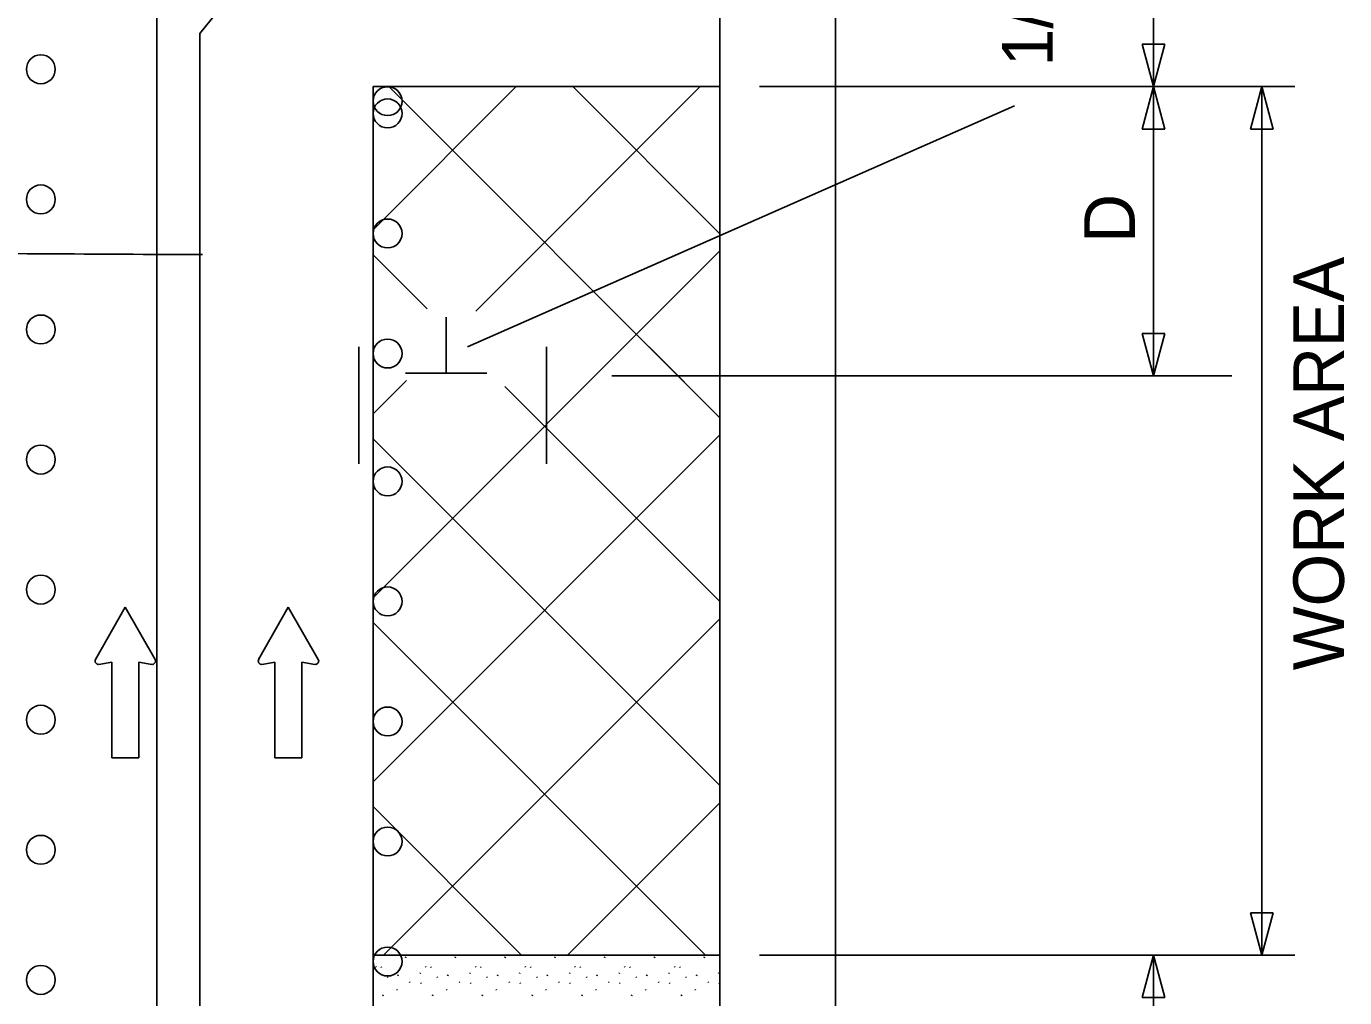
# Model space of a CAD drawing. Extents: x 16525 to 18475, y 5726 to 6926.
# Drawn here: x 16973 to 17155.5, y 6419.4 to 6553.8 of the extents above; entities that cross this region are included whole.
import ezdxf

# ---------------------------------------------------------------- set-up
doc = ezdxf.new("R2010")
doc.units = 0
for name, color, linetype in [('ALI_LEGAL_EX', 7, 'Continuous'), ('MT_SCRATCH_LEVEL_A', 7, 'Continuous'), ('MT_SCRATCH_LEVEL_E', 7, 'Continuous'), ('PAVT_EDGE_EX', 7, 'Continuous'), ('TRAFFIC_SIGNS_PR', 7, 'Continuous'), ('TYPICAL_TEXT_DIMEN_PR', 7, 'Continuous')]:
    doc.layers.add(name, color=color, linetype=linetype)

msp = doc.modelspace()

# ---------------------------------------------------------------- linework, layer by layer
at = {"layer": 'ALI_LEGAL_EX'}
for points in [[(17019, 6509.42), (17019, 6493.24)], [(17019, 6509.42), (17019, 6493.24)], [(17045, 6509.42), (17045, 6493.24)], [(17045, 6509.42), (17045, 6493.24)]]:
    msp.add_lwpolyline(points, dxfattribs=at)
at = {"layer": 'MT_SCRATCH_LEVEL_A'}
for p, q in [((17021, 6545.42), (17069, 6545.42)), ((17021, 6525.61), (17040.8, 6545.42)), ((17069, 6499.61), (17023.19, 6545.42)), ((17035.2, 6514.35), (17066.26, 6545.42)), ((17069, 6525.07), (17048.65, 6545.42)), ((17021, 6474.7), (17069, 6522.7)), ((17028.49, 6514.66), (17021, 6522.16)), ((17069, 6499.61), (17059.19, 6509.42)), ((17069, 6509.42), (17069, 6393.18)), ((17069, 6425.24), (17069, 6509.42)), ((17069, 6509.42), (17069, 6393.18)), ((17069, 6425.24), (17069, 6509.42)), ((17021, 6500.15), (17025.63, 6504.78)), ((17021, 6500.15), (17025.63, 6504.78)), ((17069, 6474.16), (17039.24, 6503.91)), ((17069, 6474.16), (17039.38, 6503.77)), ((17021, 6449.24), (17069, 6497.24)), ((17069, 6448.7), (17021, 6496.7)), ((17067, 6425.24), (17021, 6471.25)), ((17022.45, 6425.24), (17069, 6471.79)), ((17022.45, 6425.24), (17069, 6471.79)), ((17041.55, 6425.24), (17021, 6445.79)), ((17047.91, 6425.24), (17069, 6446.33)), ((17047.91, 6425.24), (17069, 6446.33)), ((17021, 6425.24), (17069, 6425.24)), ((17069, 6393.18), (17069, 6425.24)), ((17069, 6393.18), (17069, 6425.24)), ((17021.37, 6423.65), (17021.42, 6423.57)), ((17021.37, 6423.65), (17021.42, 6423.57)), ((17022.11, 6423.62), (17022.16, 6423.54)), ((17022.11, 6423.62), (17022.16, 6423.54)), ((17025.47, 6424.88), (17025.53, 6425)), ((17025.47, 6424.88), (17025.53, 6425)), ((17028.26, 6423.65), (17028.31, 6423.57)), ((17028.26, 6423.65), (17028.31, 6423.57)), ((17029, 6423.62), (17029.05, 6423.54)), ((17029, 6423.62), (17029.05, 6423.54)), ((17032.36, 6424.88), (17032.42, 6425)), ((17032.36, 6424.88), (17032.42, 6425)), ((17035.15, 6423.65), (17035.2, 6423.57)), ((17035.15, 6423.65), (17035.2, 6423.57)), ((17035.88, 6423.62), (17035.94, 6423.54)), ((17035.88, 6423.62), (17035.94, 6423.54)), ((17039.25, 6424.88), (17039.3, 6425)), ((17039.25, 6424.88), (17039.3, 6425)), ((17042.03, 6423.65), (17042.09, 6423.57)), ((17042.03, 6423.65), (17042.09, 6423.57)), ((17042.77, 6423.62), (17042.82, 6423.54)), ((17042.77, 6423.62), (17042.82, 6423.54)), ((17046.14, 6424.88), (17046.19, 6425)), ((17046.14, 6424.88), (17046.19, 6425)), ((17048.92, 6423.65), (17048.97, 6423.57)), ((17048.92, 6423.65), (17048.97, 6423.57)), ((17049.66, 6423.62), (17049.71, 6423.54)), ((17049.66, 6423.62), (17049.71, 6423.54)), ((17053.03, 6424.88), (17053.08, 6425)), ((17053.03, 6424.88), (17053.08, 6425)), ((17055.81, 6423.65), (17055.86, 6423.57)), ((17055.81, 6423.65), (17055.86, 6423.57)), ((17056.55, 6423.62), (17056.6, 6423.54)), ((17056.55, 6423.62), (17056.6, 6423.54)), ((17059.91, 6424.88), (17059.97, 6425)), ((17059.91, 6424.88), (17059.97, 6425)), ((17062.7, 6423.65), (17062.75, 6423.57)), ((17062.7, 6423.65), (17062.75, 6423.57)), ((17063.43, 6423.62), (17063.49, 6423.54)), ((17063.43, 6423.62), (17063.49, 6423.54)), ((17066.8, 6424.88), (17066.85, 6425)), ((17066.8, 6424.88), (17066.85, 6425)), ((17022.98, 6422.24), (17023.03, 6422.16)), ((17022.98, 6422.24), (17023.03, 6422.16)), ((17024.43, 6422.39), (17024.48, 6422.51)), ((17024.43, 6422.39), (17024.48, 6422.51)), ((17026.05, 6421.56), (17026.1, 6421.48)), ((17026.05, 6421.56), (17026.1, 6421.48)), ((17027.49, 6422.69), (17027.55, 6422.8)), ((17027.49, 6422.69), (17027.55, 6422.8)), ((17027.58, 6421.42), (17027.63, 6421.34)), ((17027.58, 6421.42), (17027.63, 6421.34)), ((17029.87, 6422.24), (17029.92, 6422.16)), ((17029.87, 6422.24), (17029.92, 6422.16)), ((17031.31, 6422.39), (17031.37, 6422.51)), ((17031.31, 6422.39), (17031.37, 6422.51)), ((17032.93, 6421.56), (17032.98, 6421.48)), ((17032.93, 6421.56), (17032.98, 6421.48)), ((17034.38, 6422.69), (17034.43, 6422.8)), ((17034.38, 6422.69), (17034.43, 6422.8)), ((17034.46, 6421.42), (17034.51, 6421.34)), ((17034.46, 6421.42), (17034.51, 6421.34)), ((17036.75, 6422.24), (17036.8, 6422.16)), ((17036.75, 6422.24), (17036.8, 6422.16)), ((17038.2, 6422.39), (17038.25, 6422.51)), ((17038.2, 6422.39), (17038.25, 6422.51)), ((17039.82, 6421.56), (17039.87, 6421.48)), ((17039.82, 6421.56), (17039.87, 6421.48)), ((17041.27, 6422.69), (17041.32, 6422.8)), ((17041.27, 6422.69), (17041.32, 6422.8)), ((17041.35, 6421.42), (17041.4, 6421.34)), ((17041.35, 6421.42), (17041.4, 6421.34)), ((17043.64, 6422.24), (17043.69, 6422.16)), ((17043.64, 6422.24), (17043.69, 6422.16)), ((17045.09, 6422.39), (17045.14, 6422.51)), ((17045.09, 6422.39), (17045.14, 6422.51)), ((17046.71, 6421.56), (17046.76, 6421.48)), ((17046.71, 6421.56), (17046.76, 6421.48)), ((17048.16, 6422.69), (17048.21, 6422.8)), ((17048.16, 6422.69), (17048.21, 6422.8)), ((17048.24, 6421.42), (17048.29, 6421.34)), ((17048.24, 6421.42), (17048.29, 6421.34)), ((17050.53, 6422.24), (17050.58, 6422.16)), ((17050.53, 6422.24), (17050.58, 6422.16)), ((17051.98, 6422.39), (17052.03, 6422.51)), ((17051.98, 6422.39), (17052.03, 6422.51)), ((17053.6, 6421.56), (17053.65, 6421.48)), ((17053.6, 6421.56), (17053.65, 6421.48)), ((17055.05, 6422.69), (17055.1, 6422.8)), ((17055.05, 6422.69), (17055.1, 6422.8)), ((17055.12, 6421.42), (17055.18, 6421.34)), ((17055.12, 6421.42), (17055.18, 6421.34)), ((17057.42, 6422.24), (17057.47, 6422.16)), ((17057.42, 6422.24), (17057.47, 6422.16)), ((17058.86, 6422.39), (17058.92, 6422.51)), ((17058.86, 6422.39), (17058.92, 6422.51)), ((17060.48, 6421.56), (17060.53, 6421.48)), ((17060.48, 6421.56), (17060.53, 6421.48)), ((17061.93, 6422.69), (17061.99, 6422.8)), ((17061.93, 6422.69), (17061.99, 6422.8)), ((17062.01, 6421.42), (17062.06, 6421.34)), ((17062.01, 6421.42), (17062.06, 6421.34)), ((17064.3, 6422.24), (17064.35, 6422.16)), ((17064.3, 6422.24), (17064.35, 6422.16)), ((17065.75, 6422.39), (17065.8, 6422.51)), ((17065.75, 6422.39), (17065.8, 6422.51)), ((17067.37, 6421.56), (17067.42, 6421.48)), ((17067.37, 6421.56), (17067.42, 6421.48)), ((17068.82, 6422.69), (17068.87, 6422.8)), ((17068.82, 6422.69), (17068.87, 6422.8)), ((17068.9, 6421.42), (17068.95, 6421.34)), ((17068.9, 6421.42), (17068.95, 6421.34)), ((17022.33, 6419.63), (17022.38, 6419.75)), ((17022.33, 6419.63), (17022.38, 6419.75)), ((17024.26, 6420.5), (17024.31, 6420.42)), ((17024.26, 6420.5), (17024.31, 6420.42)), ((17029.22, 6419.63), (17029.27, 6419.75)), ((17029.22, 6419.63), (17029.27, 6419.75)), ((17031.14, 6420.5), (17031.19, 6420.42)), ((17031.14, 6420.5), (17031.19, 6420.42)), ((17036.1, 6419.63), (17036.16, 6419.75)), ((17036.1, 6419.63), (17036.16, 6419.75)), ((17038.03, 6420.5), (17038.08, 6420.42)), ((17038.03, 6420.5), (17038.08, 6420.42)), ((17042.99, 6419.63), (17043.04, 6419.75)), ((17042.99, 6419.63), (17043.04, 6419.75)), ((17044.92, 6420.5), (17044.97, 6420.42)), ((17044.92, 6420.5), (17044.97, 6420.42)), ((17049.88, 6419.63), (17049.93, 6419.75)), ((17049.88, 6419.63), (17049.93, 6419.75)), ((17051.81, 6420.5), (17051.86, 6420.42)), ((17051.81, 6420.5), (17051.86, 6420.42)), ((17056.77, 6419.63), (17056.82, 6419.75)), ((17056.77, 6419.63), (17056.82, 6419.75)), ((17058.69, 6420.5), (17058.74, 6420.42)), ((17058.69, 6420.5), (17058.74, 6420.42)), ((17063.65, 6419.63), (17063.71, 6419.75)), ((17063.65, 6419.63), (17063.71, 6419.75)), ((17065.58, 6420.5), (17065.63, 6420.42)), ((17065.58, 6420.5), (17065.63, 6420.42))]:
    msp.add_line(p, q, dxfattribs=at)
at = {"layer": 'MT_SCRATCH_LEVEL_E'}
for p, q in [((16986.68, 6473.41), (16982.57, 6466.17)), ((16986.68, 6473.41), (16982.57, 6466.17)), ((16986.68, 6473.41), (16982.57, 6466.17)), ((16986.68, 6473.41), (16982.57, 6466.17)), ((16990.83, 6466.17), (16986.68, 6473.41)), ((16990.83, 6466.17), (16986.68, 6473.41)), ((16990.83, 6466.17), (16986.68, 6473.41)), ((16990.83, 6466.17), (16986.68, 6473.41)), ((17009.26, 6473.41), (17005.15, 6466.17)), ((17009.26, 6473.41), (17005.15, 6466.17)), ((17013.41, 6466.17), (17009.26, 6473.41)), ((17013.41, 6466.17), (17009.26, 6473.41)), ((16983.05, 6465.48), (16984.83, 6465.8)), ((16983.05, 6465.48), (16984.83, 6465.8)), ((16983.05, 6465.48), (16984.83, 6465.8)), ((16983.05, 6465.48), (16984.83, 6465.8)), ((16984.83, 6465.8), (16984.83, 6452.54)), ((16984.83, 6465.8), (16984.83, 6452.54)), ((16984.83, 6465.8), (16984.83, 6452.54)), ((16984.83, 6465.8), (16984.83, 6452.54)), ((16988.57, 6452.54), (16988.57, 6465.8)), ((16988.57, 6465.8), (16990.35, 6465.48)), ((16988.57, 6452.54), (16988.57, 6465.8)), ((16988.57, 6465.8), (16990.35, 6465.48)), ((16988.57, 6452.54), (16988.57, 6465.8)), ((16988.57, 6465.8), (16990.35, 6465.48)), ((16988.57, 6452.54), (16988.57, 6465.8)), ((16988.57, 6465.8), (16990.35, 6465.48)), ((17005.63, 6465.48), (17007.41, 6465.8)), ((17005.63, 6465.48), (17007.41, 6465.8)), ((17007.41, 6465.8), (17007.41, 6452.54)), ((17007.41, 6465.8), (17007.41, 6452.54)), ((17011.15, 6452.54), (17011.15, 6465.8)), ((17011.15, 6465.8), (17012.93, 6465.48)), ((17011.15, 6452.54), (17011.15, 6465.8)), ((17011.15, 6465.8), (17012.93, 6465.48)), ((16984.83, 6452.54), (16988.57, 6452.54)), ((16984.83, 6452.54), (16988.57, 6452.54)), ((16984.83, 6452.54), (16988.57, 6452.54)), ((16984.83, 6452.54), (16988.57, 6452.54)), ((17007.41, 6452.54), (17011.15, 6452.54)), ((17007.41, 6452.54), (17011.15, 6452.54))]:
    msp.add_line(p, q, dxfattribs=at)
for centre, start, end in [((16982.98, 6465.94), 150.4248, 279.9638), ((16982.98, 6465.94), 150.4248, 279.9638), ((16982.98, 6465.94), 150.4248, 279.9638), ((16982.98, 6465.94), 150.4248, 279.9638), ((16990.42, 6465.94), 260.0362, 29.7731), ((16990.42, 6465.94), 260.0362, 29.7731), ((16990.42, 6465.94), 260.0362, 29.7731), ((16990.42, 6465.94), 260.0362, 29.7731), ((17005.56, 6465.94), 150.4248, 279.9638), ((17005.56, 6465.94), 150.4248, 279.9638), ((17013, 6465.94), 260.0362, 29.7731), ((17013, 6465.94), 260.0362, 29.7731)]:
    msp.add_arc(centre, 0.463, start, end, dxfattribs=at)
at = {"layer": 'PAVT_EDGE_EX'}
for p, q in [((17069, 6926.09), (17069, 6062.8)), ((17085, 6926.09), (17085, 6062.8)), ((16991.07, 6912.1), (16991.07, 6082.91)), ((16997, 6552.78), (17045, 6612.39)), ((16997, 6552.78), (16997, 6381.96)), ((17021, 6545.42), (17021, 6393.18))]:
    msp.add_line(p, q, dxfattribs=at)
at = {"layer": 'TRAFFIC_SIGNS_PR'}
for centre in [(16975, 6547.82), (17023, 6543.41), (17023, 6541.72), (16975, 6529.82), (17023, 6525.1), (16975, 6511.82), (17023, 6508.49), (16975, 6493.82), (17023, 6490.8), (16975, 6475.82), (17023, 6474.19), (16975, 6457.82), (17023, 6457.58), (16975, 6439.82), (17023, 6440.97), (17023, 6424.36), (16975, 6421.82)]:
    msp.add_circle(centre, 2, dxfattribs=at)
at = {"layer": 'TYPICAL_TEXT_DIMEN_PR'}
for p, q in [((17129, 6563.82), (17129, 6545.42)), ((17129, 6545.42), (17127.43, 6551.28)), ((17127.43, 6551.28), (17129, 6551.28)), ((17129, 6551.28), (17130.57, 6551.28)), ((17130.57, 6551.28), (17129, 6545.42)), ((17148.57, 6545.42), (17074.5, 6545.42)), ((17127.43, 6539.55), (17129, 6545.42)), ((17129, 6505.42), (17129, 6545.42)), ((17129, 6545.42), (17130.57, 6539.55)), ((17142.43, 6539.55), (17144, 6545.42)), ((17144, 6425.24), (17144, 6545.42)), ((17144, 6545.42), (17145.57, 6539.55)), ((17109.76, 6542.77), (17034.06, 6509.43)), ((17129, 6539.55), (17127.43, 6539.55)), ((17130.57, 6539.55), (17129, 6539.55)), ((17144, 6539.55), (17142.43, 6539.55)), ((17145.57, 6539.55), (17144, 6539.55)), ((17031.13, 6505.76), (17031.13, 6513.54)), ((17129, 6505.42), (17127.43, 6511.28)), ((17127.43, 6511.28), (17129, 6511.28)), ((17129, 6511.28), (17130.57, 6511.28)), ((17130.57, 6511.28), (17129, 6505.42)), ((17036.75, 6505.76), (17025.5, 6505.76)), ((17139.87, 6505.42), (17054.06, 6505.42)), ((17144, 6425.24), (17142.43, 6431.1)), ((17142.43, 6431.1), (17144, 6431.1)), ((17144, 6425.24), (17142.43, 6431.1)), ((17142.43, 6431.1), (17144, 6431.1)), ((17144, 6431.1), (17145.57, 6431.1)), ((17145.57, 6431.1), (17144, 6425.24)), ((17144, 6431.1), (17145.57, 6431.1)), ((17145.57, 6431.1), (17144, 6425.24)), ((17148.57, 6425.24), (17074.5, 6425.24)), ((17127.43, 6419.38), (17129, 6425.24)), ((17129, 6393.18), (17129, 6425.24)), ((17129, 6425.24), (17130.57, 6419.38)), ((17129, 6419.38), (17127.43, 6419.38)), ((17130.57, 6419.38), (17129, 6419.38))]:
    msp.add_line(p, q, dxfattribs=at)
msp.add_open_spline([(16997.4, 6522.18), (16912.62, 6522.18), (16912.62, 6530.06), (16948.58, 6530.06), (16948.58, 6536.21), (16900.28, 6536.21), (16896.35, 6536.21)], degree=2, dxfattribs=at)

# ---------------------------------------------------------------- texts
for s, p in [('1/2', (17115.07, 6548.23)), ('D', (17126.44, 6523.81)), ('WORK AREA', (17155.38, 6464.66))]:
    msp.add_text(s, height=7, rotation=90, dxfattribs=at).set_placement(p)

doc.saveas('drawing.dxf')
